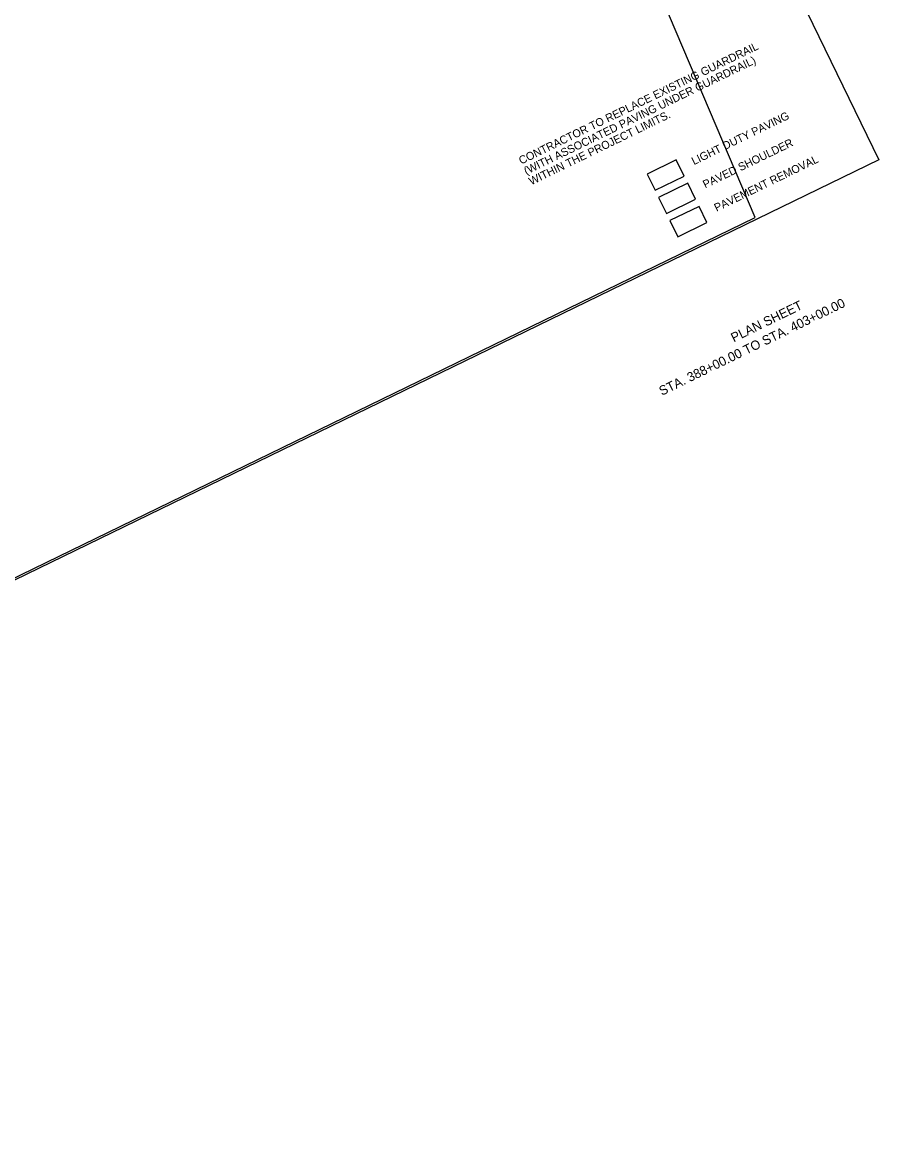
# Model space of a CAD drawing. Extents: x 1616869 to 1620470, y 1100482 to 1103335.
# Drawn here: x 1618151 to 1618793, y 1100504 to 1101340 of the extents above; entities that cross this region are included whole.
import ezdxf

# ---------------------------------------------------------------- set-up
doc = ezdxf.new("R2010")
doc.units = 0
for name, color, linetype in [('Level 2', 7, 'Continuous'), ('Level 4', 7, 'Continuous'), ('RD_EX_Control_Access', 7, 'Continuous'), ('RD_SHT_TX', 7, 'Continuous')]:
    doc.layers.add(name, color=color, linetype=linetype)

msp = doc.modelspace()

# ---------------------------------------------------------------- linework, layer by layer
at = {"layer": 'Level 2'}
msp.add_lwpolyline([(1616868.78, 1101364.63), (1618375.15, 1102097.07), (1618793.41, 1101236.86), (1617287.04, 1100504.42)], close=True, dxfattribs=at)
at = {"layer": 'Level 4'}
msp.add_lwpolyline([(1617080.14, 1101099.03), (1617256.2, 1100856.12), (1617395.1, 1100558.35), (1618700.82, 1101193.66), (1618573.12, 1101494.1), (1618454.8, 1101769.78), (1618339.83, 1102037.66), (1618182.95, 1101960.1), (1618167.86, 1101990.6), (1616961.35, 1101407.95), (1616972.59, 1101384.68), (1616914.03, 1101356.41)], close=True, dxfattribs=at)
msp.add_lwpolyline([(1617080.14, 1101099.03), (1617256.2, 1100856.12), (1617395.1, 1100558.35), (1618700.82, 1101193.66), (1618573.12, 1101494.1), (1618454.8, 1101769.78), (1618339.83, 1102037.66), (1618182.95, 1101960.1), (1618167.86, 1101990.6), (1616961.35, 1101407.95), (1616972.59, 1101384.68), (1616914.03, 1101356.41)], close=True, dxfattribs=at)
at = {"layer": 'RD_SHT_TX'}
for points in [[(1618625.74, 1101214.09), (1618647.57, 1101224.7), (1618641.68, 1101236.8), (1618619.86, 1101226.19)], [(1618634.24, 1101196.62), (1618656.06, 1101207.23), (1618650.18, 1101219.33), (1618628.36, 1101208.71)], [(1618642.74, 1101179.14), (1618664.56, 1101189.75), (1618658.68, 1101201.85), (1618636.85, 1101191.24)]]:
    msp.add_lwpolyline(points, close=True, dxfattribs=at)
for points in [[(1618625.74, 1101214.09), (1618647.57, 1101224.7), (1618641.68, 1101236.8), (1618619.86, 1101226.19), (1618625.74, 1101214.09)], [(1618634.24, 1101196.62), (1618656.06, 1101207.23), (1618650.18, 1101219.33), (1618628.36, 1101208.71), (1618634.24, 1101196.62)], [(1618642.74, 1101179.14), (1618664.56, 1101189.75), (1618658.68, 1101201.85), (1618636.85, 1101191.24), (1618642.74, 1101179.14)]]:
    msp.add_lwpolyline(points, dxfattribs=at)

# ---------------------------------------------------------------- texts
at = {"layer": 'RD_EX_Control_Access'}
for s, height, p in [('STA. 388+00.00 TO STA. 403+00.00', 6.9833, (1618630.81, 1101059.89)), ('PLAN SHEET', 6.983, (1618684.71, 1101099.9))]:
    msp.add_text(s, height=height, rotation=25.93046, dxfattribs=at).set_placement(p)
at = {"layer": 'RD_SHT_TX'}
for s, p in [('CONTRACTOR TO REPLACE EXISTING GUARDRAIL', (1618525.38, 1101233.21)), ('(WITH ASSOCIATED PAVING UNDER GUARDRAIL)', (1618529.16, 1101225.44)), ('WITHIN THE PROJECT LIMITS.', (1618532.94, 1101217.66)), ('LIGHT DUTY PAVING', (1618654.86, 1101232.78)), ('PAVED SHOULDER', (1618663.35, 1101215.3)), ('PAVEMENT REMOVAL', (1618671.85, 1101197.82))]:
    msp.add_text(s, height=6, rotation=25.93046, dxfattribs=at).set_placement(p)

doc.saveas('drawing.dxf')
